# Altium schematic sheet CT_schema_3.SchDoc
size 372 x 243 mm
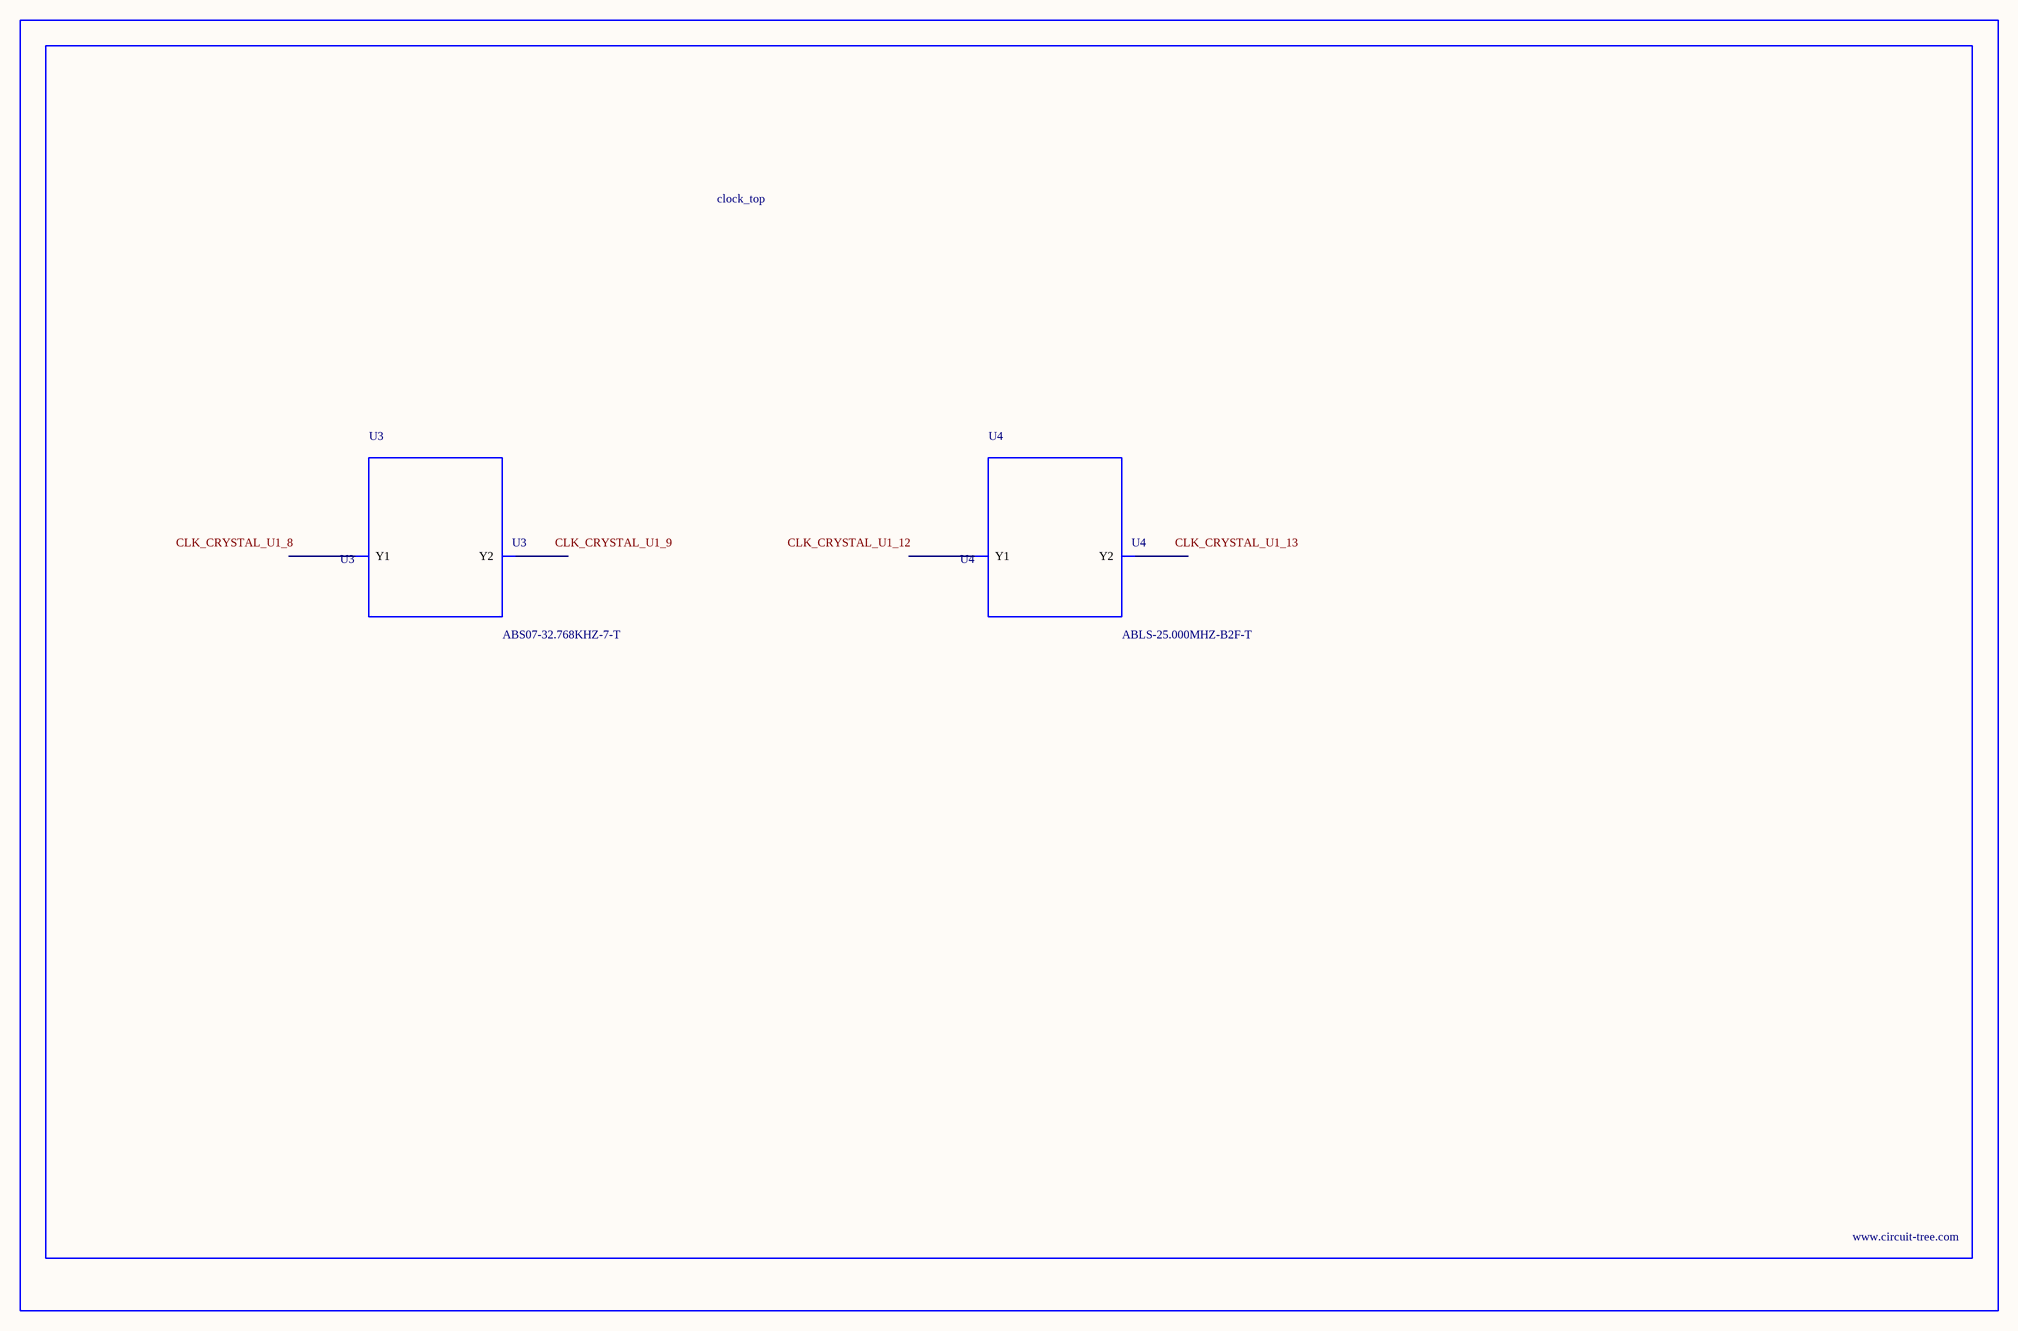
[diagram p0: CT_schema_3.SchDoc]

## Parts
BORDER2  (no value)
U3  ABS07-32.768KHZ-7-T  [ABS07-32.768KHZ-7-T]
U4  ABLS-25.000MHZ-B2F-T  [ABLS-25.000MHZ-B2F-T]

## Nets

Not connected (* = marked no-connect by the designer): U3 1(Y1) 2(Y2); U4 1(Y1) 2(Y2)

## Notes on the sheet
- Labels drawn without touching a wire or pin: CLK_CRYSTAL_U1_8, CLK_CRYSTAL_U1_9, CLK_CRYSTAL_U1_12, CLK_CRYSTAL_U1_13

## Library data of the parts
BORDER2 = BORDER_PAGE2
